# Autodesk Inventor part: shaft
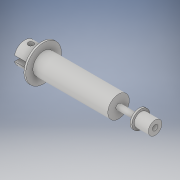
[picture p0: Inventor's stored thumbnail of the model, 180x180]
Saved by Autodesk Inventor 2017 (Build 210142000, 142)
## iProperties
Created: 2017-01
Part Number: shaft
Material: Generic
Document SubType Name: Modeling
Designer: yul067
Density: 1 g/cm^3
Appearance: Default
Author: yul067
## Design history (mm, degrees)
sketch "Sketch1"
  geometry: C1 r 6 at (0, 0); 1 further point
  constraints: 1 centre point, 1 coincident
  dimensions: "d0" = 12 diameter of C1
extrude "Extrusion1" new body sketch "Sketch1" distance "d1" = 52.5; taper "d2" = 0 deg
sketch "Sketch2"
  geometry: C1 r 1.5 at (0, 0); 1 further point
  constraints: 1 centre point, 1 coincident
  dimensions: "d3" = 3 diameter of C1
extrude "Extrusion2" join sketch "Sketch2" distance "d4" = 11.5; taper "d5" = 0 deg
sketch "Sketch3"
  geometry: C1 r 5 at (0, 0); 1 further point
  constraints: 1 centre point, 1 coincident
  dimensions: "d6" = 10 diameter of C1
extrude "Extrusion3" join sketch "Sketch3" distance "d7" = 1; taper "d8" = 0 deg
sketch "Sketch4"
  geometry: C1 r 3.75 at (0, 0); 1 further point
  constraints: 1 centre point, 1 coincident
  dimensions: "d9" = 7.5 diameter of C1
extrude "Extrusion4" join sketch "Sketch4" distance "d10" = 8; taper "d11" = 0 deg
sketch "Sketch5"
  geometry: C1 r 1.5 at (0, 0); 1 further point
  constraints: 1 centre point, 1 coincident
  dimensions: "d12" = 3 diameter of C1
extrude "Extrusion5" cut sketch "Sketch5" distance "d13" = 8; taper "d14" = 0 deg
sketch "Sketch6"
  geometry: C1 r 3.75 at (0, 0) reference; C2 r 5.5 at (0, 0); C3 r 1.5 at (0, 0) reference; C4 r 6 at (0, 0); 1 further point
  constraints: 2 centre point, 2 coincident
  dimensions: "d15" = 11 diameter of C2; "d16" = 12 diameter of C4
extrude "Extrusion6" cut sketch "Sketch6" distance "d17" = 10.5; taper "d18" = 0 deg
sketch "Sketch7"
  geometry: C1 r 10 at (0, 0); 1 further point
  constraints: 1 centre point, 1 coincident
  dimensions: "d19" = 20 diameter of C1
extrude "Extrusion7" join sketch "Sketch7" distance "d20" = 1; taper "d21" = 0 deg
sketch "Sketch8"
  geometry: L1 (-6, 1.5)-(6, 1.5); L2 (6, 1.5)-(6, -1.5); L3 (6, -1.5)-(-6, -1.5); L4 (-6, -1.5)-(-6, 1.5); L5 (-6, 1.5)-(6, -1.5); L6 (6, 1.5)-(-6, -1.5); 2 further points
  constraints: 12 end point, 2 midpoint, 2 parallel, 1 horizontal, 1 perpendicular
  dimensions: "d23" = 12 distance of L2.end L3.end
extrude "Extrusion8" cut sketch "Sketch8" distance "d24" = 9; taper "d25" = 0 deg
sketch "Sketch10"
  geometry: C1 r 6 at (0, 0); C2 r 1.5 at (0, 0) reference; C3 r 4.844 at (0, 0); 1 further point
  constraints: 2 centre point, 2 coincident
extrude "Extrusion10" join sketch "Sketch10" distance "d31" = 9.5; taper "d32" = 0 deg
sketch "Sketch12"
  geometry: L1 (-8.413, -1.5)-(8.413, -1.5); L2 (8.413, -1.5)-(8.413, 1.5); L3 (8.413, 1.5)-(-8.413, 1.5); L4 (-8.413, 1.5)-(-8.413, -1.5); L5 (-8.413, -1.5)-(8.413, 1.5); L6 (8.413, -1.5)-(-8.413, 1.5); 1 further point
  constraints: 12 end point, 2 midpoint, 2 parallel, 1 horizontal, 1 perpendicular
  dimensions: "d35" = 3 distance of L2.end L1.end
extrude "Extrusion12" cut sketch "Sketch12" distance "d36" = 9; taper "d37" = 0 deg
sketch "Sketch13"
  geometry: L1 (-3.5, 6.32)-(3.5, 6.32); L2 (3.5, 6.32)-(3.5, 5.299); L3 (3.5, 5.299)-(-3.5, 5.299); L4 (-3.5, 5.299)-(-3.5, 6.32); L5 (-3.5, 6.32)-(3.5, 5.299); L6 (3.5, 6.32)-(-3.5, 5.299); C1 r 1.5 at (3.5, 5.809); 1 further point
  constraints: 12 end point, 3 midpoint, 2 parallel, 1 centre point, 1 horizontal, 1 perpendicular
  dimensions: "d38" = 7 distance of L2.end L3.end; "d39" = 3 diameter of C1
extrude "Extrusion13" cut sketch "Sketch13" stored distance "d40" = 10; taper "d41" = 0 deg
body "Solid1"
